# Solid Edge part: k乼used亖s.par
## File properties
Author: Türk
Template: Iso Part.par
Last saved by: Türk
Revision: 5
Application: Solid Edge
Accuracy: 0,990
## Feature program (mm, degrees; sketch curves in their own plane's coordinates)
thread "unnamed Thread 1"
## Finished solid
Body 1: sheet body, 2 faces, 28 edges, 28 vertices.
  Faces by surface: plane 2
  Edges by curve: line 28
Body 2: solid body, 14 faces, 14 edges, 0 vertices.
  Faces by surface: cylinder 6, plane 5, cone 3
  Edges by curve: circle 14
Bounding box of the edges (mm): 55.000 x 15.000 x 15.000, from (-25, -7.5, -7.5) to (30, 7.5, 7.5).
Cylindrical faces by radius (mm): R0.25 x1, R4 x1, R5 x3, R7.5 x1
Conical faces (half-angle, radius in mm at the cone's reference point): 45 deg R0.25 x1, 45 deg R5.5 x1, 45 deg R7.5 x1
Planar faces by outward normal: +x 2, -x 3
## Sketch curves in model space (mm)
line (-18, 0, 3) -> (-18, 0, -7.5)
line (-25, 0, 0) -> (25, 0, 0)
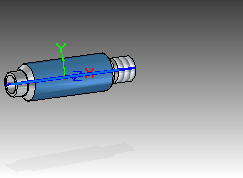
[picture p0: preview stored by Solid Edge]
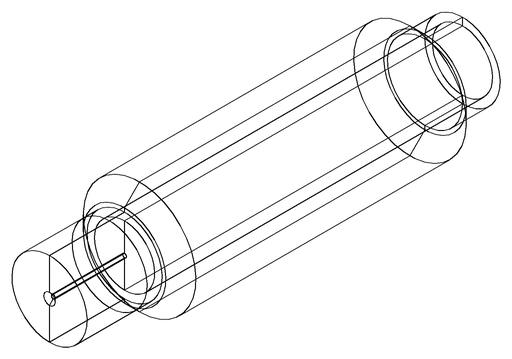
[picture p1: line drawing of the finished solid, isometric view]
